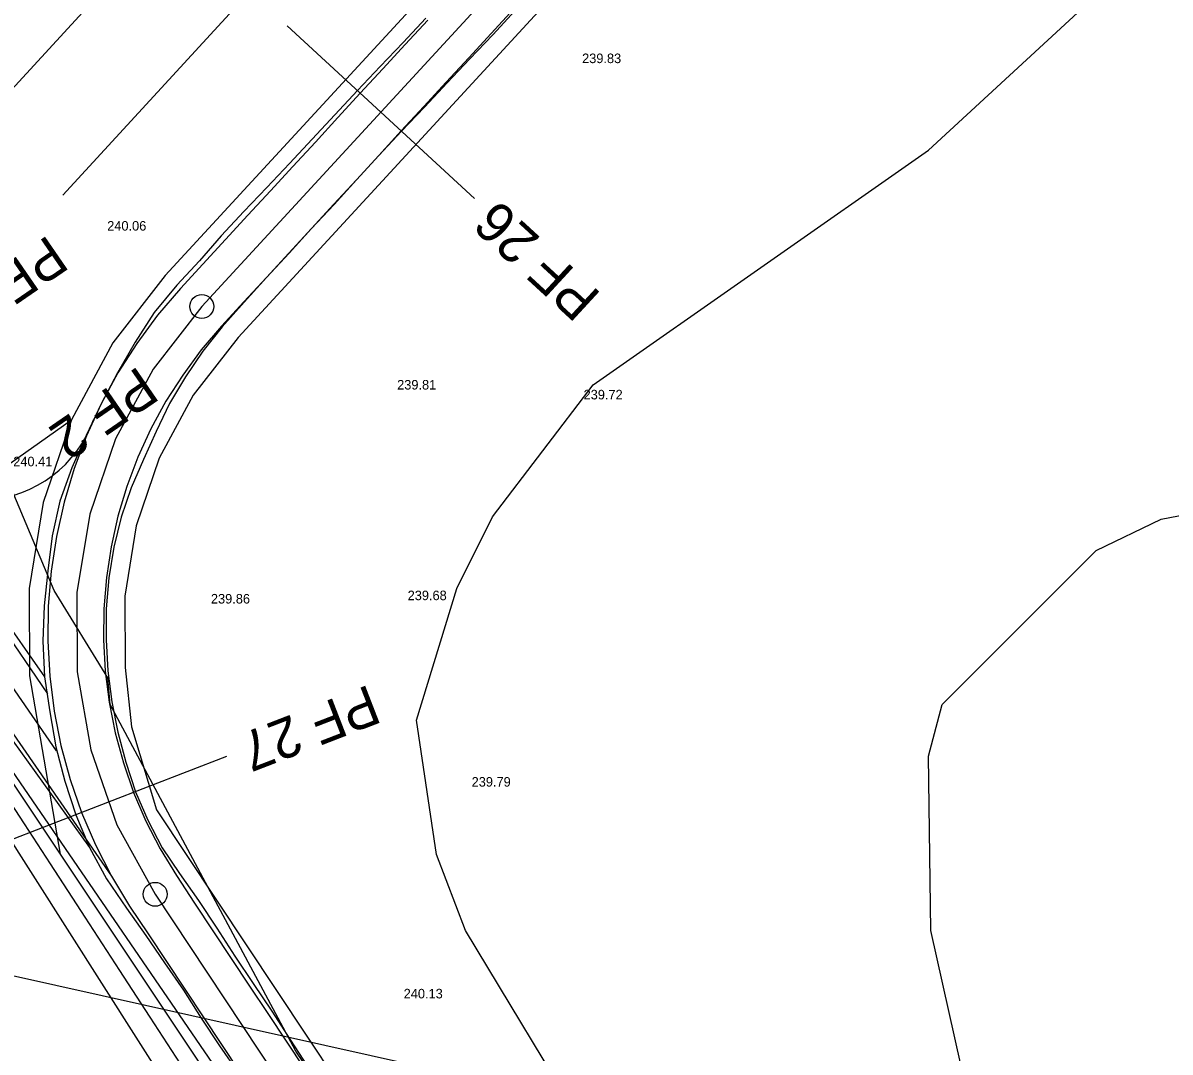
# Model space of a CAD drawing. Extents: x -555887 to -552101, y -1100251 to -1096546.
# Drawn here: x -555733.4 to -555661.3, y -1098548.4 to -1098483.8 of the extents above; entities that cross this region are included whole.
import ezdxf

# ---------------------------------------------------------------- set-up
doc = ezdxf.new("R2010")
doc.units = 0
for name, color, linetype in [('07_ELEKTRO', 7, 'Continuous'), ('IP_návrh', 7, 'Continuous'), ('PARCELY_cesty', 7, 'Continuous'), ('PARCELY_VHO', 7, 'Continuous'), ('POLYGONY_rozšíření', 7, 'Continuous'), ('POLYGONY_SITUACE_PF', 7, 'Continuous'), ('POLYGONY_SITUACE_PF_POPISY', 7, 'Continuous'), ('POLYGONY_SITUACE_PO', 7, 'Continuous'), ('vrstevnice', 7, 'Continuous'), ('Výškopis', 7, 'Continuous'), ('ZSST', 7, 'Continuous'), ('zájem', 7, 'Continuous')]:
    doc.layers.add(name, color=color, linetype=linetype)

msp = doc.modelspace()

# ---------------------------------------------------------------- linework, layer by layer
at = {"layer": '07_ELEKTRO'}
msp.add_lwpolyline([(-555159.59, -1098672.59), (-555301.63, -1098639.48), (-555454.178, -1098605.674), (-555599.279, -1098573.721), (-555745.296, -1098541.155), (-555886.81, -1098509.49)], dxfattribs=at)
at = {"layer": 'IP_návrh'}
msp.add_lwpolyline([(-555730.85, -1098494.64), (-555471.29, -1098211.98), (-555447.19, -1098191.79), (-555406.99, -1098193.78), (-555291.32, -1098130.27), (-555281.27, -1098119.66), (-555272.34, -1098101.41), (-555266.18, -1098052.11), (-555246.83, -1098023.92), (-555193.03, -1097978.41), (-554985.79, -1097744.7), (-554956.17, -1097701), (-554939.23, -1097656.04), (-554918.858, -1097601.971), (-554899.16, -1097585.1)], dxfattribs=at)
at = {"layer": 'PARCELY_cesty'}
for points in [[(-555460.12, -1098221.55), (-555719.836, -1098503.564), (-555722.666, -1098507.202), (-555724.795, -1098511.147), (-555726.242, -1098515.391), (-555726.966, -1098519.815), (-555726.947, -1098524.299), (-555726.54, -1098528.03), (-555724.98, -1098533.23)], [(-555470.071, -1098223.509), (-555661.76, -1098431.65), (-555667.019, -1098434.303), (-555680.634, -1098449.526), (-555683.11, -1098454.83), (-555724.419, -1098499.683), (-555727.709, -1098503.912), (-555730.31, -1098508.74), (-555732.082, -1098513.928), (-555732.968, -1098519.34), (-555732.945, -1098524.823), (-555731.02, -1098536.03)], [(-555746.728, -1098501.775), (-555740.398, -1098510.966), (-555735.21, -1098512.19), (-555730.31, -1098508.74)], [(-555750.86, -1098506.27), (-555731.02, -1098536.03), (-555579.56, -1098763.26), (-555574.359, -1098768.083), (-555567.523, -1098773.632), (-555557.756, -1098780.668), (-555551.79, -1098781.79), (-555519.524, -1098802.113), (-555513.631, -1098805.205), (-555507.213, -1098807.372), (-555500.534, -1098808.504), (-555493.761, -1098808.573), (-555487.06, -1098807.578), (-555480.599, -1098805.544), (-555474.537, -1098802.52), (-555469.026, -1098798.582), (-555464.285, -1098793.91), (-555430.01, -1098754.35)], [(-555724.98, -1098533.23), (-555585.414, -1098743.408), (-555580.559, -1098750.089), (-555575.199, -1098756.288), (-555569.335, -1098762.012), (-555563.009, -1098767.221), (-555556.213, -1098771.913), (-555516.527, -1098796.91), (-555511.263, -1098799.672), (-555505.743, -1098801.535), (-555499.999, -1098802.509), (-555494.173, -1098802.569), (-555488.41, -1098801.713), (-555482.853, -1098799.963), (-555477.64, -1098797.362), (-555472.899, -1098793.975), (-555468.665, -1098789.803), (-555432.8, -1098748.4)]]:
    msp.add_lwpolyline(points, dxfattribs=at)
at = {"layer": 'PARCELY_VHO'}
msp.add_lwpolyline([(-555757.22, -1098510.28), (-555752.5, -1098508.06), (-555750.86, -1098506.27), (-555731.02, -1098536.03), (-555579.56, -1098763.26), (-555581.632, -1098777.843), (-555591.69, -1098762.26), (-555630.72, -1098700.04), (-555680.24, -1098620.98), (-555692.89, -1098600.93), (-555699.02, -1098592.11), (-555708.39, -1098577.04), (-555756.35, -1098525.17)], close=True, dxfattribs=at)
at = {"layer": 'POLYGONY_rozšíření'}
msp.add_arc((-555736.102, -1098506.171), 7.623, 206.91069, 340.35543, dxfattribs=at)
at = {"layer": 'POLYGONY_SITUACE_PF'}
for p, q in [((-555710.887, -1098489.418), (-555716.771, -1098483.998)), ((-555705.002, -1098494.837), (-555710.887, -1098489.418)), ((-555720.577, -1098529.887), (-555728.038, -1098532.775)), ((-555728.038, -1098532.775), (-555735.499, -1098535.662))]:
    msp.add_line(p, q, dxfattribs=at)
at = {"layer": 'POLYGONY_SITUACE_PO'}
for p, q in [((-555458.905, -1098215.814), (-555722.128, -1098501.624)), ((-555702.543, -1098482.941), (-555703.954, -1098484.474)), ((-555702.543, -1098482.941), (-555703.954, -1098484.474)), ((-555702.446, -1098483.03), (-555703.858, -1098484.562)), ((-555708.064, -1098483.521), (-555709.491, -1098485.038)), ((-555707.94, -1098483.635), (-555709.351, -1098485.167)), ((-555703.954, -1098484.474), (-555705.365, -1098486.006)), ((-555703.954, -1098484.474), (-555705.365, -1098486.006)), ((-555703.858, -1098484.562), (-555705.287, -1098486.078)), ((-555709.491, -1098485.038), (-555710.919, -1098486.556)), ((-555709.351, -1098485.167), (-555710.763, -1098486.7)), ((-555705.365, -1098486.006), (-555706.777, -1098487.538)), ((-555705.365, -1098486.006), (-555706.777, -1098487.538)), ((-555705.287, -1098486.078), (-555706.723, -1098487.588)), ((-555710.919, -1098486.556), (-555712.352, -1098488.069)), ((-555710.763, -1098486.7), (-555712.174, -1098488.232)), ((-555706.777, -1098487.538), (-555708.188, -1098489.071)), ((-555706.777, -1098487.538), (-555708.188, -1098489.071)), ((-555706.723, -1098487.588), (-555708.149, -1098489.107)), ((-555712.352, -1098488.069), (-555713.782, -1098489.584)), ((-555712.174, -1098488.232), (-555713.585, -1098489.765)), ((-555708.188, -1098489.071), (-555709.599, -1098490.603)), ((-555708.188, -1098489.071), (-555709.599, -1098490.603)), ((-555708.149, -1098489.107), (-555709.584, -1098490.618)), ((-555713.782, -1098489.584), (-555715.195, -1098491.115)), ((-555713.585, -1098489.765), (-555714.997, -1098491.297)), ((-555709.599, -1098490.603), (-555711.011, -1098492.136)), ((-555709.599, -1098490.603), (-555711.011, -1098492.136)), ((-555709.584, -1098490.618), (-555711.011, -1098492.136)), ((-555715.195, -1098491.115), (-555716.611, -1098492.642)), ((-555714.997, -1098491.297), (-555716.408, -1098492.83)), ((-555716.611, -1098492.642), (-555718.042, -1098494.157)), ((-555711.011, -1098492.136), (-555712.422, -1098493.668)), ((-555711.011, -1098492.136), (-555712.422, -1098493.668)), ((-555711.011, -1098492.136), (-555712.421, -1098493.669)), ((-555711.011, -1098492.136), (-555711.011, -1098492.136)), ((-555711.011, -1098492.136), (-555711.011, -1098492.136)), ((-555716.408, -1098492.83), (-555717.819, -1098494.362)), ((-555718.042, -1098494.157), (-555719.481, -1098495.664)), ((-555712.422, -1098493.668), (-555713.833, -1098495.201)), ((-555712.422, -1098493.668), (-555713.833, -1098495.201)), ((-555712.421, -1098493.669), (-555713.805, -1098495.227)), ((-555717.819, -1098494.362), (-555719.231, -1098495.895)), ((-555719.481, -1098495.664), (-555720.902, -1098497.187)), ((-555713.833, -1098495.201), (-555715.245, -1098496.733)), ((-555713.833, -1098495.201), (-555715.245, -1098496.733)), ((-555713.805, -1098495.227), (-555715.245, -1098496.733)), ((-555719.231, -1098495.895), (-555720.642, -1098497.427)), ((-555715.245, -1098496.733), (-555716.656, -1098498.266)), ((-555715.245, -1098496.733), (-555716.656, -1098498.266)), ((-555715.245, -1098496.733), (-555716.646, -1098498.275)), ((-555715.245, -1098496.733), (-555715.245, -1098496.733)), ((-555715.245, -1098496.733), (-555715.245, -1098496.733)), ((-555720.902, -1098497.187), (-555722.278, -1098498.752)), ((-555720.642, -1098497.427), (-555722.053, -1098498.959)), ((-555716.656, -1098498.266), (-555718.067, -1098499.798)), ((-555716.656, -1098498.266), (-555718.067, -1098499.798)), ((-555716.646, -1098498.275), (-555718.056, -1098499.808)), ((-555722.278, -1098498.752), (-555723.697, -1098500.285)), ((-555722.053, -1098498.959), (-555723.467, -1098500.496)), ((-555718.067, -1098499.798), (-555719.479, -1098501.33)), ((-555718.067, -1098499.798), (-555719.479, -1098501.33)), ((-555718.056, -1098499.808), (-555719.456, -1098501.352)), ((-555723.697, -1098500.285), (-555725.111, -1098502.002)), ((-555723.467, -1098500.496), (-555724.9, -1098502.171)), ((-555719.479, -1098501.33), (-555720.886, -1098502.861)), ((-555719.479, -1098501.33), (-555720.886, -1098502.861)), ((-555719.456, -1098501.352), (-555720.847, -1098502.897)), ((-555725.111, -1098502.002), (-555726.317, -1098503.87)), ((-555724.9, -1098502.171), (-555726.207, -1098503.946)), ((-555722.128, -1098501.624), (-555725.188, -1098505.557)), ((-555720.886, -1098502.861), (-555722.162, -1098504.351)), ((-555720.886, -1098502.861), (-555722.162, -1098504.351)), ((-555720.847, -1098502.897), (-555722.055, -1098504.436)), ((-555726.317, -1098503.87), (-555727.414, -1098505.791)), ((-555726.207, -1098503.946), (-555727.4, -1098505.799)), ((-555722.162, -1098504.351), (-555723.324, -1098505.931)), ((-555722.162, -1098504.351), (-555723.324, -1098505.931)), ((-555722.055, -1098504.436), (-555723.157, -1098506.046)), ((-555727.414, -1098505.791), (-555728.448, -1098507.738)), ((-555725.188, -1098505.557), (-555727.554, -1098509.943)), ((-555727.4, -1098505.799), (-555728.448, -1098507.738)), ((-555723.324, -1098505.931), (-555724.386, -1098507.579)), ((-555723.324, -1098505.931), (-555724.386, -1098507.579)), ((-555723.157, -1098506.046), (-555724.148, -1098507.72)), ((-555728.448, -1098507.738), (-555729.396, -1098509.73)), ((-555728.448, -1098507.738), (-555729.372, -1098509.74)), ((-555728.448, -1098507.738), (-555728.448, -1098507.738)), ((-555728.448, -1098507.738), (-555728.448, -1098507.738)), ((-555724.386, -1098507.579), (-555725.318, -1098509.305)), ((-555724.386, -1098507.579), (-555725.318, -1098509.305)), ((-555724.148, -1098507.72), (-555724.991, -1098509.468)), ((-555731.799, -1098525.951), (-555743.462, -1098508.794)), ((-555725.318, -1098509.305), (-555726.141, -1098511.085)), ((-555725.318, -1098509.305), (-555726.141, -1098511.085)), ((-555731.253, -1098529.537), (-555744.869, -1098509.763)), ((-555729.396, -1098509.73), (-555730.288, -1098511.756)), ((-555729.372, -1098509.74), (-555730.141, -1098511.806)), ((-555727.554, -1098509.943), (-555729.162, -1098514.66)), ((-555724.991, -1098509.468), (-555725.78, -1098511.236)), ((-555726.141, -1098511.085), (-555726.824, -1098512.924)), ((-555726.141, -1098511.085), (-555726.824, -1098512.924)), ((-555725.78, -1098511.236), (-555726.563, -1098513.012)), ((-555730.288, -1098511.756), (-555731.029, -1098513.85)), ((-555730.141, -1098511.806), (-555730.777, -1098513.916)), ((-555745.614, -1098512.705), (-555729.185, -1098535.612)), ((-555726.824, -1098512.924), (-555727.391, -1098514.801)), ((-555726.824, -1098512.924), (-555727.391, -1098514.801)), ((-555739.893, -1098513.622), (-555732.002, -1098524.877)), ((-555726.563, -1098513.012), (-555727.194, -1098514.853)), ((-555731.029, -1098513.85), (-555731.51, -1098516.02)), ((-555730.777, -1098513.916), (-555731.257, -1098516.067)), ((-555729.162, -1098514.66), (-555729.967, -1098519.578)), ((-555727.391, -1098514.801), (-555727.818, -1098516.715)), ((-555727.391, -1098514.801), (-555727.818, -1098516.715)), ((-555727.194, -1098514.853), (-555727.658, -1098516.746)), ((-555742.844, -1098515.653), (-555727.797, -1098537.395)), ((-555731.51, -1098516.02), (-555731.786, -1098518.223)), ((-555731.257, -1098516.067), (-555731.592, -1098518.246)), ((-555727.818, -1098516.715), (-555728.116, -1098518.654)), ((-555727.818, -1098516.715), (-555728.116, -1098518.654)), ((-555727.658, -1098516.746), (-555727.965, -1098518.672)), ((-555731.786, -1098518.223), (-555732.013, -1098520.431)), ((-555731.592, -1098518.246), (-555731.772, -1098520.443)), ((-555728.116, -1098518.654), (-555728.276, -1098520.608)), ((-555728.116, -1098518.654), (-555728.276, -1098520.608)), ((-555727.965, -1098518.672), (-555728.126, -1098520.616)), ((-555729.967, -1098519.578), (-555729.946, -1098524.561)), ((-555732.013, -1098520.431), (-555732.112, -1098522.654)), ((-555731.772, -1098520.443), (-555731.797, -1098522.647)), ((-555728.276, -1098520.608), (-555728.298, -1098522.57)), ((-555728.276, -1098520.608), (-555728.298, -1098522.57)), ((-555728.126, -1098520.616), (-555728.138, -1098522.566)), ((-555732.112, -1098522.654), (-555732.002, -1098524.877)), ((-555731.797, -1098522.647), (-555731.676, -1098524.848)), ((-555728.298, -1098522.57), (-555728.191, -1098524.528)), ((-555728.298, -1098522.57), (-555728.191, -1098524.528)), ((-555728.138, -1098522.566), (-555728.021, -1098524.512)), ((-555728.021, -1098524.512), (-555727.782, -1098526.447)), ((-555732.002, -1098524.877), (-555731.677, -1098527.08)), ((-555731.676, -1098524.848), (-555731.396, -1098527.034)), ((-555729.946, -1098524.561), (-555729.101, -1098529.472)), ((-555728.191, -1098524.528), (-555727.941, -1098526.473)), ((-555728.191, -1098524.528), (-555727.941, -1098526.473)), ((-555727.941, -1098526.473), (-555727.565, -1098528.398)), ((-555727.941, -1098526.473), (-555727.565, -1098528.398)), ((-555727.782, -1098526.447), (-555727.4, -1098528.359)), ((-555731.677, -1098527.08), (-555731.295, -1098529.273)), ((-555731.396, -1098527.034), (-555730.972, -1098529.197)), ((-555727.565, -1098528.398), (-555727.045, -1098530.289)), ((-555727.565, -1098528.398), (-555727.045, -1098530.289)), ((-555727.4, -1098528.359), (-555726.901, -1098530.245)), ((-555731.295, -1098529.273), (-555730.732, -1098531.429)), ((-555730.972, -1098529.197), (-555730.389, -1098531.323)), ((-555729.101, -1098529.472), (-555727.455, -1098534.176)), ((-555726.901, -1098530.245), (-555726.296, -1098532.101)), ((-555727.045, -1098530.289), (-555726.406, -1098532.143)), ((-555727.045, -1098530.289), (-555726.406, -1098532.143)), ((-555730.732, -1098531.429), (-555730.033, -1098533.547)), ((-555730.389, -1098531.323), (-555729.67, -1098533.407)), ((-555726.406, -1098532.143), (-555725.632, -1098533.945)), ((-555726.406, -1098532.143), (-555725.632, -1098533.945)), ((-555726.296, -1098532.101), (-555725.523, -1098533.894)), ((-555730.033, -1098533.547), (-555729.185, -1098535.612)), ((-555729.67, -1098533.407), (-555728.8, -1098535.432)), ((-555727.455, -1098534.176), (-555725.052, -1098538.542)), ((-555725.632, -1098533.945), (-555724.739, -1098535.692)), ((-555725.632, -1098533.945), (-555724.739, -1098535.692)), ((-555725.523, -1098533.894), (-555724.624, -1098535.627)), ((-555729.185, -1098535.612), (-555728.111, -1098537.569)), ((-555728.8, -1098535.432), (-555727.797, -1098537.395)), ((-555724.739, -1098535.692), (-555723.724, -1098537.37)), ((-555724.739, -1098535.692), (-555723.724, -1098537.37)), ((-555724.624, -1098535.627), (-555723.529, -1098537.243)), ((-555727.797, -1098537.395), (-555726.656, -1098539.281)), ((-555723.724, -1098537.37), (-555722.584, -1098539.095)), ((-555723.724, -1098537.37), (-555722.584, -1098539.095)), ((-555723.529, -1098537.243), (-555722.333, -1098538.929)), ((-555728.111, -1098537.569), (-555726.862, -1098539.415)), ((-555725.052, -1098538.542), (-555587.878, -1098745.121)), ((-555726.862, -1098539.415), (-555725.644, -1098541.127)), ((-555726.656, -1098539.281), (-555725.5, -1098541.032)), ((-555722.584, -1098539.095), (-555721.432, -1098540.831)), ((-555722.584, -1098539.095), (-555721.432, -1098540.831)), ((-555722.333, -1098538.929), (-555721.19, -1098540.671)), ((-555725.5, -1098541.032), (-555724.348, -1098542.767)), ((-555721.432, -1098540.831), (-555720.279, -1098542.567)), ((-555721.432, -1098540.831), (-555720.279, -1098542.567)), ((-555721.19, -1098540.671), (-555720.059, -1098542.42)), ((-555725.644, -1098541.127), (-555724.458, -1098542.841)), ((-555720.059, -1098542.42), (-555718.891, -1098544.146)), ((-555724.458, -1098542.841), (-555723.277, -1098544.557)), ((-555724.348, -1098542.767), (-555723.195, -1098544.503)), ((-555720.279, -1098542.567), (-555719.127, -1098544.302)), ((-555720.279, -1098542.567), (-555719.127, -1098544.302)), ((-555723.277, -1098544.557), (-555722.175, -1098546.326)), ((-555723.195, -1098544.503), (-555722.043, -1098546.238)), ((-555719.127, -1098544.302), (-555717.974, -1098546.038)), ((-555719.127, -1098544.302), (-555717.974, -1098546.038)), ((-555718.891, -1098544.146), (-555717.733, -1098545.877)), ((-555717.974, -1098546.038), (-555716.822, -1098547.773)), ((-555717.974, -1098546.038), (-555716.822, -1098547.773)), ((-555717.733, -1098545.877), (-555716.607, -1098547.63)), ((-555722.175, -1098546.326), (-555721.018, -1098548.058)), ((-555722.043, -1098546.238), (-555720.89, -1098547.974)), ((-555721.018, -1098548.058), (-555719.826, -1098549.768)), ((-555720.89, -1098547.974), (-555719.738, -1098549.709)), ((-555716.822, -1098547.773), (-555715.67, -1098549.509)), ((-555716.822, -1098547.773), (-555715.67, -1098549.509)), ((-555716.607, -1098547.63), (-555715.467, -1098549.374))]:
    msp.add_line(p, q, dxfattribs=at)
for centre in [(-555722.128, -1098501.624), (-555725.052, -1098538.542)]:
    msp.add_circle(centre, 0.75, dxfattribs=at)
at = {"layer": 'vrstevnice'}
for points in [[(-555606.559, -1098680.67), (-555643.909, -1098636.3), (-555664.129, -1098607.65), (-555682.529, -1098579.01), (-555705.559, -1098540.81), (-555707.379, -1098536.04), (-555708.649, -1098527.61), (-555706.119, -1098519.33), (-555703.869, -1098514.84), (-555697.549, -1098506.55), (-555676.489, -1098491.81), (-555665.259, -1098481.42), (-555656.409, -1098470.32), (-555640.119, -1098446.87), (-555622.429, -1098415.14), (-555616.669, -1098406.29), (-555611.899, -1098400.96), (-555603.049, -1098394.08), (-555595.329, -1098389.58), (-555587.469, -1098386.92)], [(-555606.559, -1098680.67), (-555643.909, -1098636.3), (-555664.129, -1098607.65), (-555682.529, -1098579.01), (-555705.559, -1098540.81), (-555707.379, -1098536.04), (-555708.649, -1098527.61), (-555706.119, -1098519.33), (-555703.869, -1098514.84), (-555697.549, -1098506.55), (-555676.489, -1098491.81), (-555665.259, -1098481.42), (-555656.409, -1098470.32), (-555640.119, -1098446.87), (-555622.429, -1098415.14), (-555616.669, -1098406.29), (-555611.899, -1098400.96), (-555603.049, -1098394.08), (-555595.329, -1098389.58), (-555587.469, -1098386.92)], [(-555694.706, -1098607.545), (-555688.525, -1098599.368), (-555686.629, -1098595.09), (-555688.989, -1098587.29), (-555697.269, -1098573.95), (-555705.559, -1098564.12), (-555716.229, -1098548.4), (-555727.879, -1098526.63), (-555728.019, -1098524.95), (-555731.389, -1098519.47), (-555740.379, -1098498.13)], [(-555585.639, -1098585.47), (-555599.259, -1098586.45), (-555627.059, -1098584.76), (-555638.859, -1098582.09), (-555652.899, -1098577.18), (-555658.659, -1098573.95), (-555668.349, -1098565.39), (-555670.589, -1098561.03), (-555674.099, -1098550.92), (-555676.349, -1098540.81), (-555676.489, -1098529.86), (-555675.649, -1098526.63), (-555665.979, -1098516.96), (-555661.889, -1098514.98), (-555650.929, -1098512.87), (-555637.449, -1098512.17), (-555587.749, -1098513.71)]]:
    msp.add_lwpolyline(points, dxfattribs=at)
at = {"layer": 'ZSST'}
for points in [[(-555765.1, -1098488.39), (-555754.67, -1098504.46), (-555748.03, -1098514.96), (-555736.93, -1098530.79), (-555721.96, -1098554.3), (-555693.93, -1098598.39), (-555667.96, -1098639.29), (-555651.43, -1098664.81), (-555630.02, -1098697.77), (-555614.72, -1098720.24), (-555609.86, -1098730.23)], [(-555583.09, -1098783.14), (-555578.35, -1098765.76), (-555579.94, -1098761.61), (-555586.95, -1098750.47), (-555602.11, -1098729.09), (-555610.49, -1098716.56), (-555625.36, -1098695.37), (-555647.98, -1098661.72), (-555663.92, -1098637.15), (-555690.5, -1098596.36), (-555718.88, -1098552.89), (-555735.07, -1098529.28), (-555745.86, -1098513.94), (-555753.49, -1098503.56), (-555763.78, -1098488.05)], [(-555745.86, -1098513.94), (-555736.03, -1098529.93), (-555720.77, -1098553.38), (-555692.4, -1098597.22), (-555666.55, -1098637.59), (-555649.49, -1098663.65), (-555627.54, -1098696.45), (-555612.53, -1098718.03)], [(-555283.1, -1098643.91), (-555301.63, -1098639.48), (-555454.178, -1098605.674), (-555599.279, -1098573.721), (-555745.296, -1098541.155), (-555792.66, -1098530.65)]]:
    msp.add_lwpolyline(points, dxfattribs=at)
at = {"layer": 'zájem'}
for points in [[(-555493.09, -1098225.57), (-555626.26, -1098371.34), (-555629.84, -1098374.5), (-555752.5, -1098508.06), (-555757.22, -1098510.28), (-555756.35, -1098525.17), (-555708.39, -1098577.04), (-555699.02, -1098592.11), (-555692.89, -1098600.93), (-555680.24, -1098620.98), (-555630.69, -1098700.04), (-555591.69, -1098762.26), (-555552.95, -1098822.28), (-555538.97, -1098843.94), (-555527.81, -1098868.73), (-555518, -1098858.71), (-555456.8, -1098789.9), (-555379.7, -1098701.24)], [(-555379.7, -1098701.24), (-555456.8, -1098789.9), (-555518, -1098858.71), (-555527.81, -1098868.73), (-555538.97, -1098843.94), (-555552.95, -1098822.28), (-555591.69, -1098762.26), (-555630.69, -1098700.04), (-555680.24, -1098620.98), (-555692.89, -1098600.93), (-555699.02, -1098592.11), (-555708.39, -1098577.04), (-555756.35, -1098525.17), (-555757.22, -1098510.28), (-555752.5, -1098508.06), (-555629.84, -1098374.5), (-555626.26, -1098371.34), (-555493.09, -1098225.57)]]:
    msp.add_lwpolyline(points, dxfattribs=at)

# ---------------------------------------------------------------- texts
at = {"layer": 'POLYGONY_SITUACE_PF_POPISY'}
for s, rotation, p in [('PF 26', 137.35579, (-555696.969, -1098500.876)), ('PF 1', 214.55162, (-555731.745, -1098497.084)), ('PF 2', 214.55162, (-555726.074, -1098505.32)), ('PF 27', 201.15769, (-555711.613, -1098525.345))]:
    msp.add_text(s, height=2.5, rotation=rotation, dxfattribs=at).set_placement(p)
at = {"layer": 'Výškopis'}
for s, p in [('239.83', (-555698.248, -1098486.34)), ('240.06', (-555728.065, -1098496.86)), ('239.81', (-555709.86, -1098506.84)), ('239.72', (-555698.154, -1098507.46)), ('240.41', (-555733.964, -1098511.66)), ('239.68', (-555709.2, -1098520.07)), ('239.86', (-555721.552, -1098520.28)), ('239.79', (-555705.183, -1098531.78)), ('240.13', (-555709.45, -1098545.08))]:
    msp.add_text(s, height=0.6, dxfattribs=at).set_placement(p)

doc.saveas('drawing.dxf')
